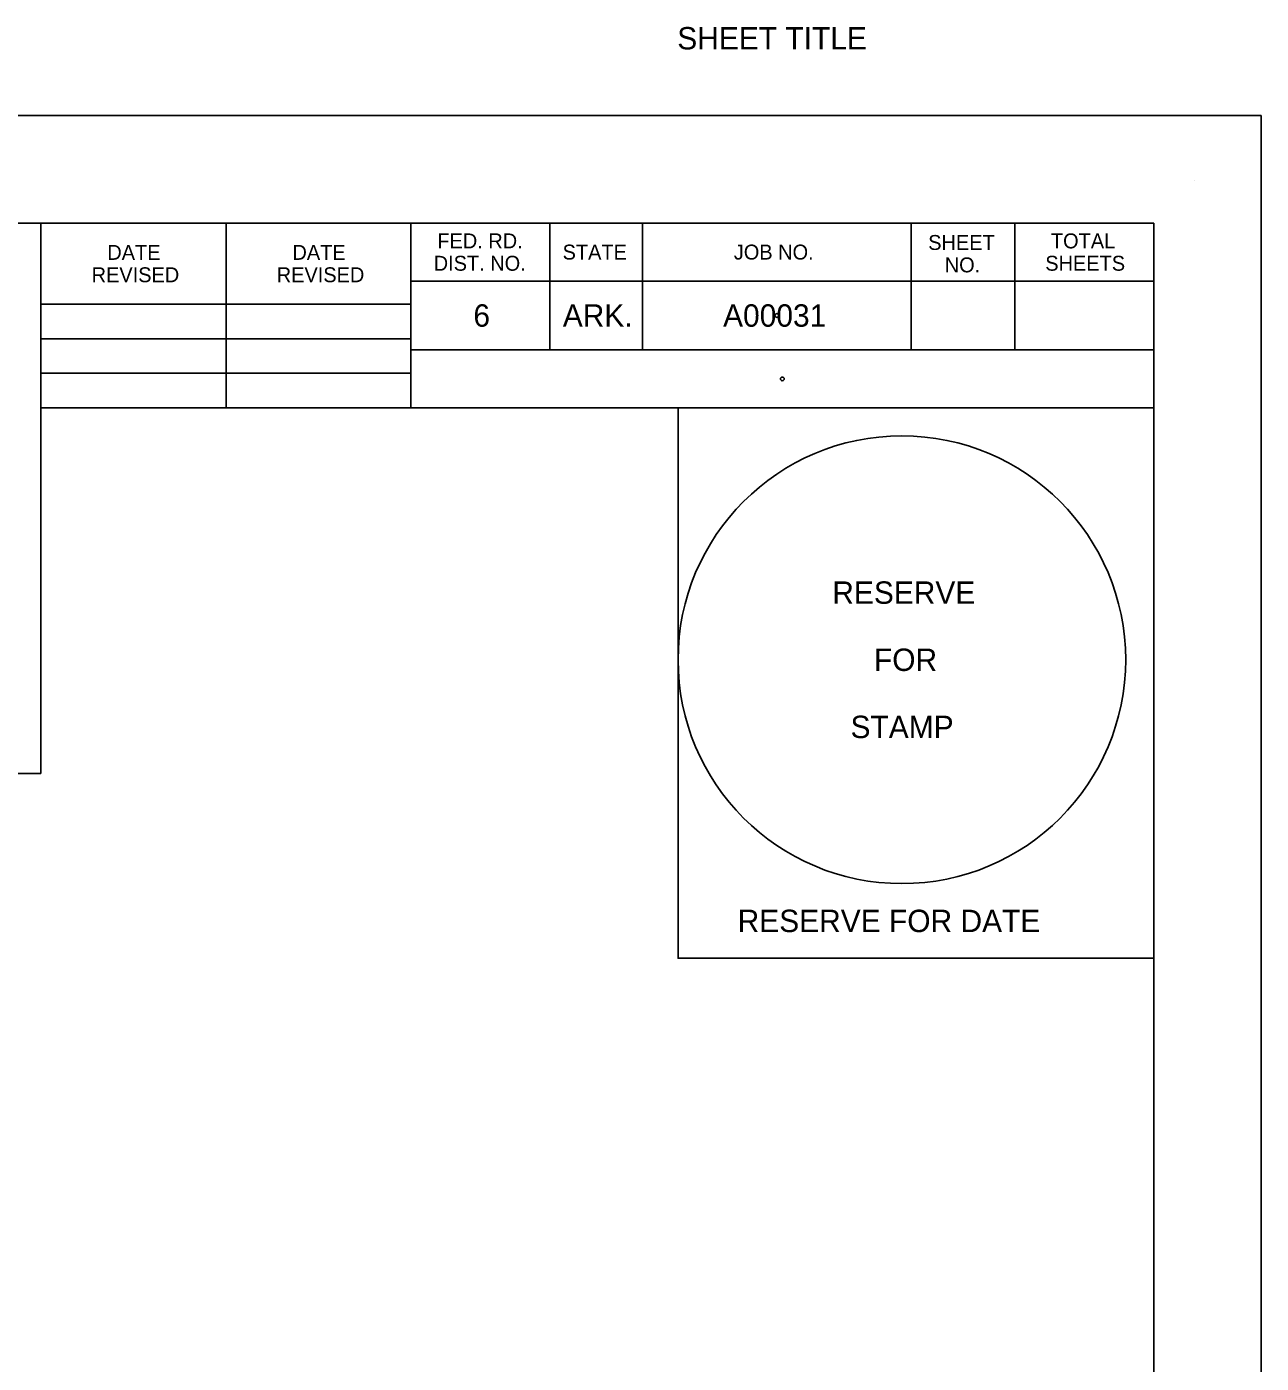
# Model space of a CAD drawing. Extents: x 0 to 19, y -0.6 to 11.2.
# Drawn here: x 13.691 to 17, y 7.655 to 11.238 of the extents above; entities that cross this region are included whole.
import ezdxf

# ---------------------------------------------------------------- set-up
doc = ezdxf.new("R2010")
doc.units = 0
for name, color, linetype in [('G-ANNO-TEXT', 7, 'Continuous'), ('G-Border-Paper', 7, 'Continuous'), ('G-Border-Sheet', 7, 'Continuous'), ('G-No Plot-Anchor', 7, 'Continuous'), ('G-No Plot-Border-1', 7, 'Continuous'), ('G-No Plot-Border-2', 7, 'Continuous'), ('G-No Plot-Stamp-1', 7, 'Continuous'), ('G-Table-Major', 7, 'Continuous'), ('G-Table-Minor', 7, 'Continuous')]:
    doc.layers.add(name, color=color, linetype=linetype)

msp = doc.modelspace()

# ---------------------------------------------------------------- linework, layer by layer
at = {"layer": 'G-ANNO-TEXT'}
msp.add_line((16.821, 10.8269), (16.821, 10.8269), dxfattribs=at)
at = {"layer": 'G-Border-Paper'}
msp.add_lwpolyline([(17, 11), (0, 11), (0, 0), (17, 0)], close=True, dxfattribs=at)
at = {"layer": 'G-Border-Sheet'}
for p in [(0.758, 10.7116), (16.7116, 5.5)]:
    msp.add_line(p, (16.7116, 10.7116), dxfattribs=at)
at = {"layer": 'G-No Plot-Anchor'}
for centre in [(15.7013, 10.4639), (15.7161, 10.2939)]:
    msp.add_circle(centre, 0.005, dxfattribs=at)
at = {"layer": 'G-No Plot-Border-1'}
msp.add_lwpolyline([(0.758, 5.5), (0.758, 10.7116), (13.7281, 10.7116), (13.7281, 10.2161), (14.7206, 10.2161), (14.8024, 10.2161), (15.4366, 10.2161), (15.4366, 8.7411), (16.7116, 8.7411), (16.7116, 5.5)], close=True, dxfattribs=at)
at = {"layer": 'G-No Plot-Border-2'}
msp.add_lwpolyline([(0.758, 5.5), (0.758, 10.7116), (12.3781, 10.7116), (12.3781, 9.2366), (13.7281, 9.2366), (13.7281, 10.2161), (14.7206, 10.2161), (14.9256, 10.2161), (16.7116, 10.2161), (16.7116, 5.5)], close=True, dxfattribs=at)
at = {"layer": 'G-No Plot-Stamp-1'}
msp.add_circle((16.0366, 9.5411), 0.6, dxfattribs=at)
at = {"layer": 'G-Table-Major'}
for p, q in [((13.7281, 10.2168), (13.7281, 10.7116)), ((14.7206, 10.7116), (14.7206, 10.2161)), ((13.7281, 10.4946), (14.7206, 10.4946)), ((16.7116, 10.2161), (13.7281, 10.2161))]:
    msp.add_line(p, q, dxfattribs=at)
at = {"layer": 'G-Table-Minor'}
for p, q in [((14.2256, 10.2165), (14.2256, 10.7116)), ((15.0926, 10.7116), (15.0926, 10.3716)), ((15.3411, 10.7116), (15.3411, 10.3716)), ((16.0616, 10.7116), (16.0616, 10.3716)), ((16.3396, 10.7116), (16.3396, 10.3716)), ((16.7116, 10.5561), (14.7206, 10.5561)), ((16.7116, 10.5656), (16.7116, 10.5656)), ((13.7281, 10.4011), (14.7206, 10.4011)), ((16.7116, 10.3716), (14.7206, 10.3716)), ((13.7281, 10.3096), (14.7206, 10.3096))]:
    msp.add_line(p, q, dxfattribs=at)

# ---------------------------------------------------------------- texts
at = {"layer": 'G-ANNO-TEXT'}
for s, height, p in [('SHEET TITLE', 0.06, (15.4345, 11.1771)), ('FED. RD.', 0.04, (14.7913, 10.6439)), ('SHEET', 0.04, (16.1072, 10.6396)), ('TOTAL', 0.04, (16.4361, 10.6439)), ('DATE', 0.04, (13.9066, 10.6131)), ('DATE', 0.04, (14.4029, 10.6131)), ('STATE', 0.04, (15.1271, 10.6139)), ('JOB NO.', 0.04, (15.5861, 10.6139)), ('DIST. NO.', 0.04, (14.7816, 10.5839)), ('NO.', 0.04, (16.1515, 10.5796)), ('SHEETS', 0.04, (16.421, 10.5839)), ('REVISED', 0.04, (13.8646, 10.5531)), ('REVISED', 0.04, (14.3608, 10.5531)), ('6', 0.06, (14.8879, 10.4339)), ('ARK.', 0.06, (15.1276, 10.4339)), ('A00031', 0.06, (15.5573, 10.4339))]:
    msp.add_text(s, height=height, dxfattribs=at).set_placement(p)
at = {"layer": 'G-No Plot-Stamp-1'}
for s, p in [('RESERVE', (15.85, 9.6911)), ('FOR ', (15.9617, 9.5111)), ('STAMP', (15.8989, 9.3311)), ('RESERVE FOR DATE', (15.5963, 8.8111))]:
    msp.add_text(s, height=0.06, dxfattribs=at).set_placement(p)

doc.saveas('drawing.dxf')
